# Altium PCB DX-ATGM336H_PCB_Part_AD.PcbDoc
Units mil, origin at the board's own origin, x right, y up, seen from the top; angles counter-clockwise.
Board outline 6000 x 4000 mil, 2 copper layers (Top Layer, Bottom Layer); 1 components, 0 nets, 36 pads, 0 vias.
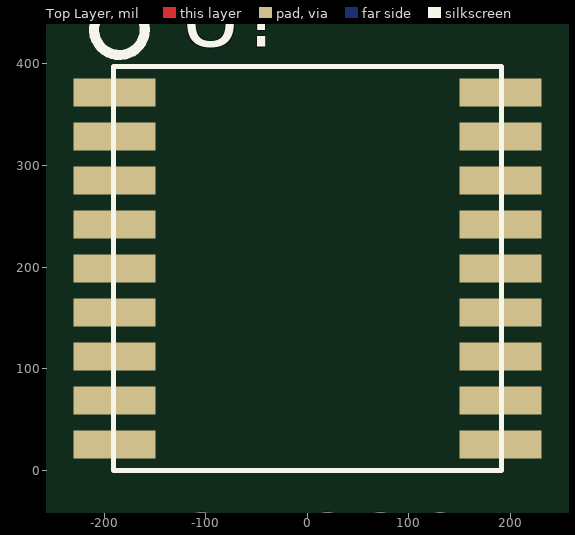
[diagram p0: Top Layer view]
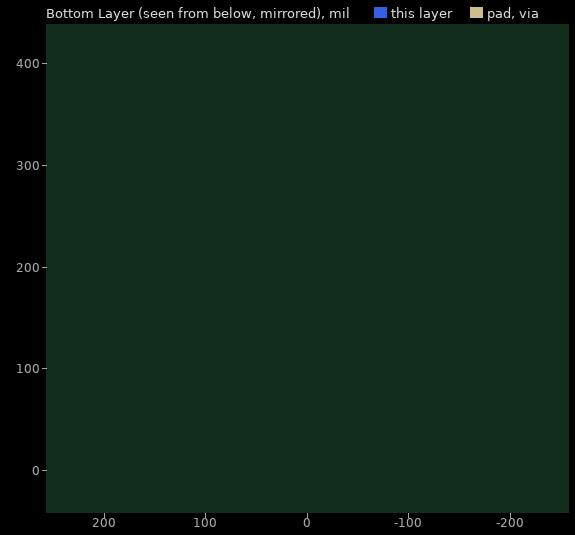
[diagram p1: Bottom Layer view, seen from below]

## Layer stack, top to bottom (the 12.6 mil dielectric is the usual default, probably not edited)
Top Solder: solder mask 0.4, Solder Resist, Dk 3.5
Top Layer: signal copper 1.4
Dielectric 1: dielectric 12.6, FR-4, Dk 4.8
Bottom Layer: signal copper 1.4
Bottom Solder: solder mask 0.4, Solder Resist, Dk 3.5

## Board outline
-2834.96,-1617.95 3165.04,-1617.95 3165.04,2382.05 -2834.96,2382.05

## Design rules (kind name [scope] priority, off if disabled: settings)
Clearance [All] p1: gap=10 ignorepadtopadclearanceinfootprint=FALSE except(0: Arc-Hole Track-Hole SMDPad-Hole THPad-Hole Via-Hole Fill-Hole Poly-Hole Region-Hole Text-Hole)
PolygonConnect [All] p1: connectstyle=Relief reliefconductorwidth=10 reliefentries=4 polygonreliefangle="90 Angle" airgapwidth=10
RoutingVias [All] p1: holewidth=28 width=50 viastyle="Through Hole" minholewidth=28 minwidth=50 maxholewidth=28 maxwidth=50
SolderMaskExpansion [All] p1: expansion=4 istentingtop=FALSE
Width [All] p1: maxlimit=10 minlimit=10 preferedwidth=10
30 further rules are at their usual default settings.

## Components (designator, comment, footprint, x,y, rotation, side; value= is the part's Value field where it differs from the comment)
U? "ATGM336H" N10_BLGA_18P 0,198.82 r270 top

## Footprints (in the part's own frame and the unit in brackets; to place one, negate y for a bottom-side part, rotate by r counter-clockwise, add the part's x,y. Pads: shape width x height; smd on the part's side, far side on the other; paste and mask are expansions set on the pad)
N10_BLGA_18P [mm]
  rect 0.7x2.05 smd: 1(-4.4,-4.825) 2(-3.3,-4.825) 3(-2.2,-4.825) 4(-1.1,-4.825) 5(0,-4.825) 6(1.1,-4.825) 7(2.2,-4.825) 8(3.3,-4.825) 9(4.4,-4.825) 10(4.4,4.825) 11(3.3,4.825) 12(2.2,4.825) 13(1.1,4.825) 14(0,4.825) 15(-1.1,4.825) 16(-2.2,4.825) 17(-3.3,4.825) 18(-4.4,4.825)
  rect 0.7x2.05 on Top Solder: 1(-4.4,-4.825) 2(-3.3,-4.825) 3(-2.2,-4.825) 4(-1.1,-4.825) 5(0,-4.825) 6(1.1,-4.825) 7(2.2,-4.825) 8(3.3,-4.825) 9(4.4,-4.825) 10(4.4,4.825) 11(3.3,4.825) 12(2.2,4.825) 13(1.1,4.825) 14(0,4.825) 15(-1.1,4.825) 16(-2.2,4.825) 17(-3.3,4.825) 18(-4.4,4.825)
  silkscreen extent -6.6,-5.33 5.05,4.85

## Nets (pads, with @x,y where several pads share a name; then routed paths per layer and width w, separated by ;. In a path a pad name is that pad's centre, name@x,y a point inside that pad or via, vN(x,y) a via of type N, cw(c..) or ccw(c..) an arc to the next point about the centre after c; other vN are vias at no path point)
pads on no net: U?.1 U?.2 U?.3 U?.4 U?.5 U?.6 U?.7 U?.8 U?.9 U?.10 U?.11 U?.12 U?.13 U?.14 U?.15 U?.16 U?.17 U?.18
